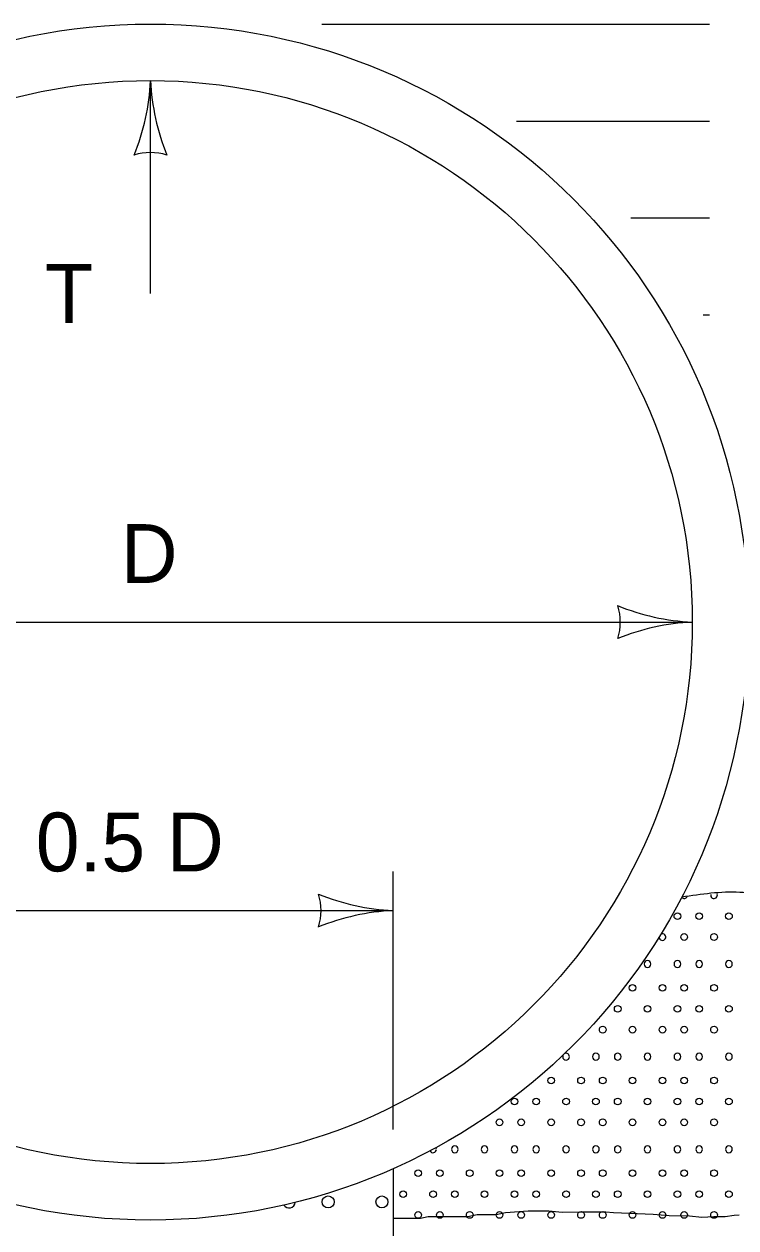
# Model space of a CAD drawing. Extents: x 49991.4 to 50021, y 49987.6 to 50011.4.
# Drawn here: x 50012.784 to 50013.51, y 50005.7 to 50006.929 of the extents above; entities that cross this region are included whole.
import ezdxf

# ---------------------------------------------------------------- set-up
doc = ezdxf.new("R2010")
doc.units = 0
for name, color, linetype in [('Level 1', 7, 'Continuous'), ('Level 2', 7, 'Continuous'), ('Level 3', 7, 'Continuous')]:
    doc.layers.add(name, color=color, linetype=linetype)

msp = doc.modelspace()

# ---------------------------------------------------------------- linework, layer by layer
at = {"layer": 'Level 1'}
for p, q in [((50013.0877, 50006.9286), (50013.4832, 50006.9286)), ((50013.286, 50006.8296), (50013.4832, 50006.8296)), ((50013.4832, 50006.7306), (50013.4028, 50006.7306)), ((50013.4832, 50006.6316), (50013.4766, 50006.6316)), ((50013.1602, 50005.76), (50013.1602, 50005.6506))]:
    msp.add_line(p, q, dxfattribs=at)
msp.add_lwpolyline([(50013.1602, 50005.7094), (50013.1883, 50005.7094), (50013.1961, 50005.7113), (50013.2366, 50005.7113), (50013.2462, 50005.7133), (50013.2655, 50005.7133), (50013.2751, 50005.7152), (50013.2982, 50005.7171), (50013.3193, 50005.7169), (50013.3326, 50005.7156), (50013.3522, 50005.7161), (50013.3773, 50005.7161), (50013.385, 50005.7153), (50013.4255, 50005.7135), (50013.4418, 50005.7123), (50013.4626, 50005.7121), (50013.4752, 50005.7105), (50013.4876, 50005.7111), (50013.499, 50005.7111), (50013.5084, 50005.7125), (50013.5134, 50005.713)], dxfattribs=at)
for centre, radius in [((50012.9127, 50006.3181), 0.6105), ((50012.9127, 50006.3181), 0.5528), ((50013.4503, 50006.0179), 0.00341), ((50013.4725, 50006.0179), 0.00341), ((50013.5029, 50006.0179), 0.00341), ((50013.5029, 50006.0179), 0.00341), ((50013.4572, 50005.9966), 0.00341), ((50013.4877, 50005.9966), 0.00341), ((50013.4046, 50005.9447), 0.00341), ((50013.4351, 50005.9447), 0.00341), ((50013.4572, 50005.9447), 0.00341), ((50013.4877, 50005.9447), 0.00341), ((50013.3894, 50005.9233), 0.00341), ((50013.4198, 50005.9233), 0.00341), ((50013.4198, 50005.9233), 0.00341), ((50013.4503, 50005.9233), 0.00341), ((50013.4725, 50005.9233), 0.00341), ((50013.5029, 50005.9233), 0.00341), ((50013.5029, 50005.9233), 0.00341), ((50013.3741, 50005.902), 0.00341), ((50013.4046, 50005.902), 0.00341), ((50013.4351, 50005.902), 0.00341), ((50013.4572, 50005.902), 0.00341), ((50013.4877, 50005.902), 0.00341), ((50013.3215, 50005.8501), 0.00341), ((50013.352, 50005.8501), 0.00341), ((50013.3741, 50005.8501), 0.00341), ((50013.4046, 50005.8501), 0.00341), ((50013.4351, 50005.8501), 0.00341), ((50013.4572, 50005.8501), 0.00341), ((50013.4877, 50005.8501), 0.00341), ((50013.2841, 50005.8287), 0.00341), ((50013.3063, 50005.8287), 0.00341), ((50013.3367, 50005.8287), 0.00341), ((50013.3367, 50005.8287), 0.00341), ((50013.3672, 50005.8287), 0.00341), ((50013.3894, 50005.8287), 0.00341), ((50013.4198, 50005.8287), 0.00341), ((50013.4198, 50005.8287), 0.00341), ((50013.4503, 50005.8287), 0.00341), ((50013.4725, 50005.8287), 0.00341), ((50013.5029, 50005.8287), 0.00341), ((50013.5029, 50005.8287), 0.00341), ((50013.2689, 50005.8074), 0.00341), ((50013.291, 50005.8074), 0.00341), ((50013.3215, 50005.8074), 0.00341), ((50013.352, 50005.8074), 0.00341), ((50013.3741, 50005.8074), 0.00341), ((50013.4046, 50005.8074), 0.00341), ((50013.4351, 50005.8074), 0.00341), ((50013.4572, 50005.8074), 0.00341), ((50013.4877, 50005.8074), 0.00341), ((50013.1858, 50005.7555), 0.00341), ((50013.2079, 50005.7555), 0.00341), ((50013.2384, 50005.7555), 0.00341), ((50013.2689, 50005.7555), 0.00341), ((50013.291, 50005.7555), 0.00341), ((50013.3215, 50005.7555), 0.00341), ((50013.352, 50005.7555), 0.00341), ((50013.3741, 50005.7555), 0.00341), ((50013.4046, 50005.7555), 0.00341), ((50013.4351, 50005.7555), 0.00341), ((50013.4572, 50005.7555), 0.00341), ((50013.4877, 50005.7555), 0.00341), ((50013.094, 50005.7261), 0.00613), ((50013.1489, 50005.7261), 0.00613), ((50013.1489, 50005.7261), 0.00613), ((50013.1705, 50005.7341), 0.00341), ((50013.1705, 50005.7341), 0.00341), ((50013.201, 50005.7341), 0.00341), ((50013.2232, 50005.7341), 0.00341), ((50013.2536, 50005.7341), 0.00341), ((50013.2536, 50005.7341), 0.00341), ((50013.2841, 50005.7341), 0.00341), ((50013.3063, 50005.7341), 0.00341), ((50013.3367, 50005.7341), 0.00341), ((50013.3367, 50005.7341), 0.00341), ((50013.3672, 50005.7341), 0.00341), ((50013.3894, 50005.7341), 0.00341), ((50013.4198, 50005.7341), 0.00341), ((50013.4198, 50005.7341), 0.00341), ((50013.4503, 50005.7341), 0.00341), ((50013.4725, 50005.7341), 0.00341), ((50013.5029, 50005.7341), 0.00341), ((50013.5029, 50005.7341), 0.00341), ((50013.1858, 50005.7128), 0.00341), ((50013.2079, 50005.7128), 0.00341), ((50013.2384, 50005.7128), 0.00341), ((50013.2689, 50005.7128), 0.00341), ((50013.291, 50005.7128), 0.00341), ((50013.3215, 50005.7128), 0.00341), ((50013.352, 50005.7128), 0.00341), ((50013.3741, 50005.7128), 0.00341), ((50013.4046, 50005.7128), 0.00341), ((50013.4351, 50005.7128), 0.00341), ((50013.4572, 50005.7128), 0.00341), ((50013.4877, 50005.7128), 0.00341)]:
    msp.add_circle(centre, radius, dxfattribs=at)
for centre, radius, start, end in [((50013.4572, 50006.0393), 0.00341, 220.6481, 339.5297), ((50013.4877, 50006.0393), 0.00341, 166.6919, 22.7337), ((50013.4351, 50005.9966), 0.00341, 180.644, 116.1275), ((50013.4198, 50005.9692), 0.00341, 0, 180), ((50013.4198, 50005.969), 0.00341, 180, 0), ((50013.4198, 50005.969), 0.00341, 180, 0), ((50013.4503, 50005.9692), 0.00341, 0, 180), ((50013.4503, 50005.969), 0.00341, 180, 0), ((50013.4725, 50005.9692), 0.00341, 0, 180), ((50013.4725, 50005.969), 0.00341, 180, 0), ((50013.5029, 50005.9692), 0.00341, 0, 180), ((50013.5029, 50005.969), 0.00341, 180, 0), ((50013.5029, 50005.969), 0.00341, 180, 0), ((50013.3367, 50005.8746), 0.00341, 0, 110.2347), ((50013.3672, 50005.8746), 0.00341, 0, 180), ((50013.3894, 50005.8746), 0.00341, 0, 180), ((50013.4198, 50005.8746), 0.00341, 0, 180), ((50013.4503, 50005.8746), 0.00341, 0, 180), ((50013.4725, 50005.8746), 0.00341, 0, 180), ((50013.5029, 50005.8746), 0.00341, 0, 180), ((50013.3367, 50005.8746), 0.00341, 157.1832, 180), ((50013.3367, 50005.8744), 0.00341, 180, 0), ((50013.3367, 50005.8744), 0.00341, 180, 0), ((50013.3672, 50005.8744), 0.00341, 180, 0), ((50013.3894, 50005.8744), 0.00341, 180, 0), ((50013.4198, 50005.8744), 0.00341, 180, 0), ((50013.4198, 50005.8744), 0.00341, 180, 0), ((50013.4503, 50005.8744), 0.00341, 180, 0), ((50013.4725, 50005.8744), 0.00341, 180, 0), ((50013.5029, 50005.8744), 0.00341, 180, 0), ((50013.5029, 50005.8744), 0.00341, 180, 0), ((50013.201, 50005.7798), 0.00341, 206.0483, 0), ((50013.201, 50005.78), 0.00341, 0, 28.642), ((50013.2232, 50005.78), 0.00341, 0, 180), ((50013.2232, 50005.7798), 0.00341, 180, 0), ((50013.2536, 50005.78), 0.00341, 0, 180), ((50013.2536, 50005.7798), 0.00341, 180, 0), ((50013.2536, 50005.7798), 0.00341, 180, 0), ((50013.2841, 50005.78), 0.00341, 0, 180), ((50013.2841, 50005.7798), 0.00341, 180, 0), ((50013.3063, 50005.78), 0.00341, 0, 180), ((50013.3063, 50005.7798), 0.00341, 180, 0), ((50013.3367, 50005.78), 0.00341, 0, 180), ((50013.3367, 50005.7798), 0.00341, 180, 0), ((50013.3367, 50005.7798), 0.00341, 180, 0), ((50013.3672, 50005.78), 0.00341, 0, 180), ((50013.3672, 50005.7798), 0.00341, 180, 0), ((50013.3894, 50005.78), 0.00341, 0, 180), ((50013.3894, 50005.7798), 0.00341, 180, 0), ((50013.4198, 50005.78), 0.00341, 0, 180), ((50013.4198, 50005.7798), 0.00341, 180, 0), ((50013.4198, 50005.7798), 0.00341, 180, 0), ((50013.4503, 50005.78), 0.00341, 0, 180), ((50013.4503, 50005.7798), 0.00341, 180, 0), ((50013.4725, 50005.78), 0.00341, 0, 180), ((50013.4725, 50005.7798), 0.00341, 180, 0), ((50013.5029, 50005.78), 0.00341, 0, 180), ((50013.5029, 50005.7798), 0.00341, 180, 0), ((50013.5029, 50005.7798), 0.00341, 180, 0), ((50013.0542, 50005.7261), 0.00613, 210.651, 356.2223)]:
    msp.add_arc(centre, radius, start, end, dxfattribs=at)
msp.add_spline([(50013.455, 50006.0376), (50013.5141, 50006.0425), (50013.5695, 50006.0356), (50013.6207, 50006.0356), (50013.7505, 50006.0308), (50013.7679, 50006.0302), (50013.8233, 50006.0356), (50013.8519, 50006.0325), (50013.9192, 50006.024)], degree=3, dxfattribs=at)
at = {"layer": 'Level 3'}
for p, q in [((50012.9127, 50006.6536), (50012.9127, 50006.8709)), ((50012.36, 50006.3181), (50013.4655, 50006.3181)), ((50013.1602, 50005.8), (50013.1602, 50006.0636)), ((50012.6652, 50006.0236), (50013.1602, 50006.0236))]:
    msp.add_line(p, q, dxfattribs=at)
for centre, radius, start, end in [((50012.6906, 50006.88), 0.2223, 337.456, 357.6395), ((50013.1454, 50006.8824), 0.233, 182.8273, 202.0772), ((50012.9127, 50006.7427), 0.0548, 72.1388, 107.8612), ((50013.4746, 50006.5403), 0.2223, 247.456, 267.6395), ((50013.3373, 50006.3181), 0.0548, 342.1388, 17.8612), ((50013.477, 50006.0854), 0.233, 92.8273, 112.0772), ((50013.1694, 50006.2458), 0.2223, 247.456, 267.6395), ((50013.032, 50006.0236), 0.0548, 342.1388, 17.8612), ((50013.1717, 50005.7909), 0.233, 92.8273, 112.0772)]:
    msp.add_arc(centre, radius, start, end, dxfattribs=at)

# ---------------------------------------------------------------- texts
at = {"layer": 'Level 2'}
for s, p in [('T', (50012.8051, 50006.6236)), ('D', (50012.8824, 50006.3581)), ('0.5 D', (50012.7957, 50006.0636))]:
    msp.add_text(s, height=0.06, dxfattribs=at).set_placement(p)

doc.saveas('drawing.dxf')
